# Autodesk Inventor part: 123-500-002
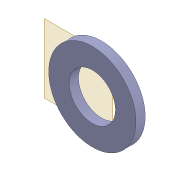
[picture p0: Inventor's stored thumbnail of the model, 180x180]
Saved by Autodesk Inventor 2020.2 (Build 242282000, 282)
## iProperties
Manager: www.cadconsulting.pl
Company: Fabian Stasiak CAD Consulting
Created: 2019-11
Part Number: 123-500-002
Material: Stal
Document SubType Name: Modeling
Designer: F.Stasiak
Mass: 287347 g
Surface Area: 12190.9 cm^2
Volume: 36604.7 cm^3
Density: 7.85 g/cm^3
Appearance: Szaroniebieska
Description: Podstawa prowadnicy
Author: F.Stasiak
Subject: Zbiór ćwiczeń. Autodesk Inventor 2020. Kurs podstawowy
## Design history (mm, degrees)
node "Płaszczyzna konstrukcyjna1"
sketch "Szkic1"
  geometry: C1 r 225 at (0, 0); C2 r 425 at (0, 0); 1 further point
  constraints: 2 centre point, 2 coincident
  dimensions: "d0" = 450 diameter of C1; "d1" = 850 diameter of C2
extrude "Wyciągnięcie proste1" new body sketch "Szkic1" distance "d2" = 90; taper "d3" = 0 deg
node "Otwory1"
node "Otwory2"
node "Bryła1"
sketch "Szkic2"
  geometry: 8 further points
hole "Otwór1" sketch "Szkic2" diameter "d4" = 17.294; stored, may be unused: countersink angle "d8" = 90 deg, drill point angle "d10" = 120 deg; dims "d5" = 69.19259, "d6" = 4, "d7" = 2, "d9" = 79.19259
sketch "Szkic3"
  geometry: 8 further points
hole "Otwór2" sketch "Szkic3" diameter "d11" = 17.294; stored, may be unused: countersink angle "d15" = 90 deg, drill point angle "d17" = 120 deg; dims "d12" = 35.34864, "d13" = 4, "d14" = 2, "d16" = 45.34865
